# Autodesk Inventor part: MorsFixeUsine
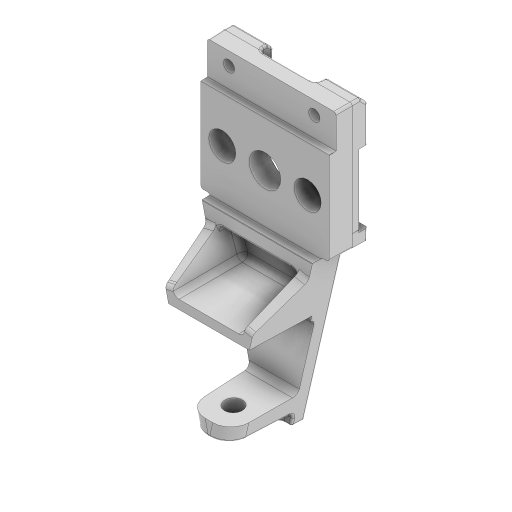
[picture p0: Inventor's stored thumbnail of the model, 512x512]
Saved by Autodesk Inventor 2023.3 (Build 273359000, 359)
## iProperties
Created: 2024-11
Part Number: MorsFixeUsine
Material: Générique
Description: STEP AP203
Document SubType Name: Modeling
Designer: Thier
Density: 1 g/cm^3
Appearance: Par défaut
Title: MorsFixeUsine.STEP
Revision Number: ANY
Sending System: SolidWorks 2017
Preprocessor: SwSTEP 2.0
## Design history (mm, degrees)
feature "Enlèv. mat.-Extru.15"
node "Solide1"
